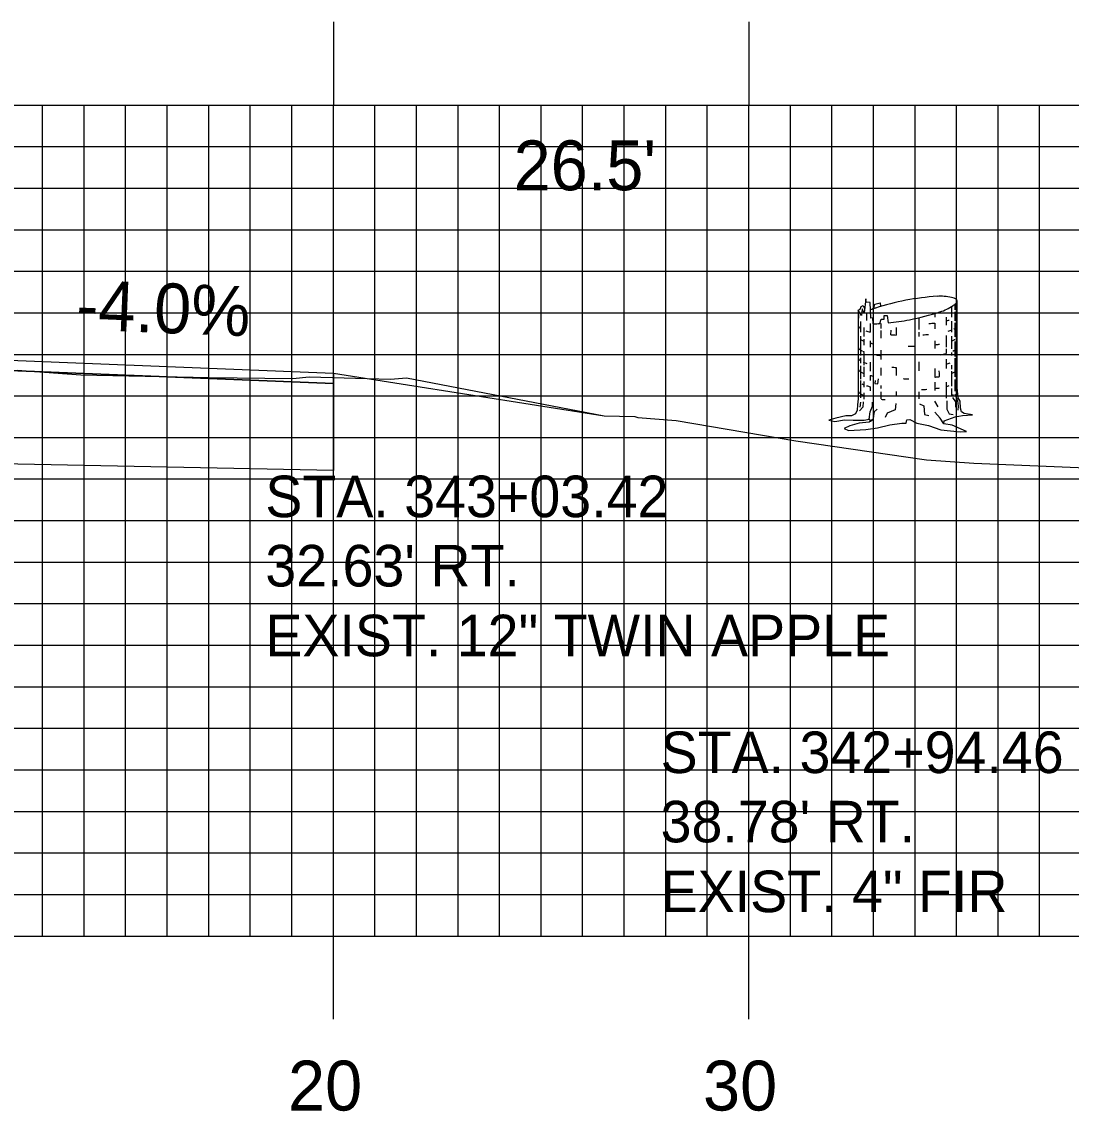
# Model space of a CAD drawing. Extents: x 1825147 to 1825490, y 442591 to 442811.
# Drawn here: x 1825324.86 to 1825350.12, y 442684.45 to 442710.67 of the extents above; entities that cross this region are included whole.
import ezdxf

# ---------------------------------------------------------------- set-up
doc = ezdxf.new("R2010")
doc.units = 0
for name, color, linetype in [('ANNOTATION', 7, 'Continuous'), ('D_Roadway_Edge_Shoulder', 7, 'Continuous'), ('D_Roadway_SubGrade', 7, 'Continuous'), ('D_Text_Monospaced', 7, 'Continuous'), ('D_Text_Standard', 7, 'Continuous'), ('H_V ANNOTATION', 7, 'Continuous'), ('MAJOR', 7, 'Continuous'), ('MINOR', 7, 'Continuous'), ('S_Roadway_Centerline', 7, 'Continuous'), ('S_Trees_Decid_Pay', 7, 'Continuous')]:
    doc.layers.add(name, color=color, linetype=linetype)

msp = doc.modelspace()

# ---------------------------------------------------------------- linework, layer by layer
at = {"layer": 'ANNOTATION'}
msp.add_line((1825332.361, 442702.213), (1825338.877, 442701.185), dxfattribs=at)
at = {"layer": 'D_Roadway_Edge_Shoulder'}
msp.add_lwpolyline([(1825324.361, 442702.533), (1825332.361, 442702.213), (1825332.361, 442701.963), (1825324.361, 442702.283)], close=True, dxfattribs=at)
at = {"layer": 'D_Roadway_SubGrade'}
msp.add_lwpolyline([(1825300.361, 442700.033), (1825292.361, 442699.873), (1825292.361, 442702.213), (1825292.361, 442701.963), (1825300.361, 442702.283), (1825312.361, 442702.523), (1825324.361, 442702.283), (1825332.361, 442701.963), (1825332.361, 442702.213), (1825332.361, 442699.873), (1825324.361, 442700.033), (1825312.361, 442700.273)], close=True, dxfattribs=at)
at = {"layer": 'MAJOR'}
for p, q in [((1825332.361, 442710.669), (1825332.361, 442708.665)), ((1825342.361, 442710.669), (1825342.361, 442708.665)), ((1825172.361, 442708.665), (1825452.361, 442708.665)), ((1825172.361, 442708.665), (1825452.361, 442708.665)), ((1825172.361, 442708.665), (1825452.361, 442708.665)), ((1825332.361, 442688.665), (1825332.361, 442708.665)), ((1825332.361, 442688.665), (1825332.361, 442708.665)), ((1825342.361, 442688.665), (1825342.361, 442708.665)), ((1825342.361, 442688.665), (1825342.361, 442708.665)), ((1825172.361, 442703.665), (1825452.361, 442703.665)), ((1825172.361, 442703.665), (1825452.361, 442703.665)), ((1825172.361, 442698.665), (1825452.361, 442698.665)), ((1825172.361, 442698.665), (1825452.361, 442698.665)), ((1825172.361, 442693.665), (1825452.361, 442693.665)), ((1825172.361, 442693.665), (1825452.361, 442693.665)), ((1825172.361, 442688.665), (1825452.361, 442688.665)), ((1825172.361, 442688.665), (1825452.361, 442688.665)), ((1825172.361, 442688.665), (1825452.361, 442688.665)), ((1825332.361, 442686.661), (1825332.361, 442688.665)), ((1825342.361, 442686.661), (1825342.361, 442688.665))]:
    msp.add_line(p, q, dxfattribs=at)
at = {"layer": 'MINOR'}
for p, q in [((1825325.361, 442688.665), (1825325.361, 442708.665)), ((1825325.361, 442688.665), (1825325.361, 442708.665)), ((1825326.361, 442688.665), (1825326.361, 442708.665)), ((1825326.361, 442688.665), (1825326.361, 442708.665)), ((1825327.361, 442688.665), (1825327.361, 442708.665)), ((1825327.361, 442688.665), (1825327.361, 442708.665)), ((1825328.361, 442688.665), (1825328.361, 442708.665)), ((1825328.361, 442688.665), (1825328.361, 442708.665)), ((1825329.361, 442688.665), (1825329.361, 442708.665)), ((1825329.361, 442688.665), (1825329.361, 442708.665)), ((1825330.361, 442688.665), (1825330.361, 442708.665)), ((1825330.361, 442688.665), (1825330.361, 442708.665)), ((1825331.361, 442688.665), (1825331.361, 442708.665)), ((1825331.361, 442688.665), (1825331.361, 442708.665)), ((1825333.361, 442688.665), (1825333.361, 442708.665)), ((1825333.361, 442688.665), (1825333.361, 442708.665)), ((1825334.361, 442688.665), (1825334.361, 442708.665)), ((1825334.361, 442688.665), (1825334.361, 442708.665)), ((1825335.361, 442688.665), (1825335.361, 442708.665)), ((1825335.361, 442688.665), (1825335.361, 442708.665)), ((1825336.361, 442688.665), (1825336.361, 442708.665)), ((1825336.361, 442688.665), (1825336.361, 442708.665)), ((1825337.361, 442688.665), (1825337.361, 442708.665)), ((1825337.361, 442688.665), (1825337.361, 442708.665)), ((1825338.361, 442688.665), (1825338.361, 442708.665)), ((1825338.361, 442688.665), (1825338.361, 442708.665)), ((1825339.361, 442688.665), (1825339.361, 442708.665)), ((1825339.361, 442688.665), (1825339.361, 442708.665)), ((1825340.361, 442688.665), (1825340.361, 442708.665)), ((1825340.361, 442688.665), (1825340.361, 442708.665)), ((1825341.361, 442688.665), (1825341.361, 442708.665)), ((1825341.361, 442688.665), (1825341.361, 442708.665)), ((1825343.361, 442688.665), (1825343.361, 442708.665)), ((1825343.361, 442688.665), (1825343.361, 442708.665)), ((1825344.361, 442688.665), (1825344.361, 442708.665)), ((1825344.361, 442688.665), (1825344.361, 442708.665)), ((1825345.361, 442688.665), (1825345.361, 442708.665)), ((1825345.361, 442688.665), (1825345.361, 442708.665)), ((1825346.361, 442688.665), (1825346.361, 442708.665)), ((1825346.361, 442688.665), (1825346.361, 442708.665)), ((1825347.361, 442688.665), (1825347.361, 442708.665)), ((1825347.361, 442688.665), (1825347.361, 442708.665)), ((1825348.361, 442688.665), (1825348.361, 442708.665)), ((1825348.361, 442688.665), (1825348.361, 442708.665)), ((1825349.361, 442688.665), (1825349.361, 442708.665)), ((1825349.361, 442688.665), (1825349.361, 442708.665)), ((1825172.361, 442707.665), (1825452.361, 442707.665)), ((1825172.361, 442707.665), (1825452.361, 442707.665)), ((1825172.361, 442706.665), (1825452.361, 442706.665)), ((1825172.361, 442706.665), (1825452.361, 442706.665)), ((1825172.361, 442705.665), (1825452.361, 442705.665)), ((1825172.361, 442705.665), (1825452.361, 442705.665)), ((1825172.361, 442704.665), (1825452.361, 442704.665)), ((1825172.361, 442704.665), (1825452.361, 442704.665)), ((1825172.361, 442702.665), (1825452.361, 442702.665)), ((1825172.361, 442702.665), (1825452.361, 442702.665)), ((1825172.361, 442701.665), (1825452.361, 442701.665)), ((1825172.361, 442701.665), (1825452.361, 442701.665)), ((1825172.361, 442700.665), (1825452.361, 442700.665)), ((1825172.361, 442700.665), (1825452.361, 442700.665)), ((1825172.361, 442699.665), (1825452.361, 442699.665)), ((1825172.361, 442699.665), (1825452.361, 442699.665)), ((1825172.361, 442697.665), (1825452.361, 442697.665)), ((1825172.361, 442697.665), (1825452.361, 442697.665)), ((1825172.361, 442696.665), (1825452.361, 442696.665)), ((1825172.361, 442696.665), (1825452.361, 442696.665)), ((1825172.361, 442695.665), (1825452.361, 442695.665)), ((1825172.361, 442695.665), (1825452.361, 442695.665)), ((1825172.361, 442694.665), (1825452.361, 442694.665)), ((1825172.361, 442694.665), (1825452.361, 442694.665)), ((1825172.361, 442692.665), (1825452.361, 442692.665)), ((1825172.361, 442692.665), (1825452.361, 442692.665)), ((1825172.361, 442691.665), (1825452.361, 442691.665)), ((1825172.361, 442691.665), (1825452.361, 442691.665)), ((1825172.361, 442690.665), (1825452.361, 442690.665)), ((1825172.361, 442690.665), (1825452.361, 442690.665)), ((1825172.361, 442689.665), (1825452.361, 442689.665)), ((1825172.361, 442689.665), (1825452.361, 442689.665))]:
    msp.add_line(p, q, dxfattribs=at)
at = {"layer": 'S_Roadway_Centerline'}
msp.add_lwpolyline([(1825324.751, 442702.284), (1825326.279, 442702.169), (1825329.368, 442702.108), (1825331.382, 442702.082), (1825331.777, 442702.121), (1825333.735, 442702.064), (1825334.12, 442702.1), (1825338.877, 442701.185), (1825339.617, 442701.17), (1825339.689, 442701.142), (1825340.614, 442701.071), (1825343.489, 442700.583), (1825346.64, 442700.125), (1825347.777, 442700.042), (1825350.864, 442699.915), (1825354.395, 442699.942), (1825358.764, 442699.53), (1825359.047, 442699.947), (1825360.34, 442700.695)], dxfattribs=at)
at = {"layer": 'S_Trees_Decid_Pay'}
for p, q in [((1825345.195, 442703.655), (1825345.195, 442703.48)), ((1825346.835, 442703.647), (1825346.835, 442703.56)), ((1825347.239, 442703.813), (1825347.239, 442703.56)), ((1825347.319, 442703.858), (1825347.319, 442703.737)), ((1825347.319, 442703.685), (1825347.319, 442703.472)), ((1825345.045, 442703.454), (1825345.045, 442703.2)), ((1825345.279, 442703.406), (1825345.279, 442703.201)), ((1825345.541, 442703.408), (1825345.541, 442703.288)), ((1825346.451, 442703.546), (1825346.451, 442703.265)), ((1825346.835, 442703.419), (1825346.835, 442703.28)), ((1825347.107, 442703.56), (1825347.107, 442703.368)), ((1825347.239, 442703.464), (1825347.239, 442703.2)), ((1825347.319, 442703.426), (1825347.319, 442703.088)), ((1825345.045, 442703.103), (1825345.045, 442702.634)), ((1825345.131, 442703.309), (1825345.131, 442703.097)), ((1825345.541, 442703.237), (1825345.541, 442703.052)), ((1825345.779, 442703.136), (1825345.784, 442703.243)), ((1825345.905, 442703.309), (1825345.905, 442703.129)), ((1825346.451, 442703.2), (1825346.451, 442703.097)), ((1825347.107, 442703.117), (1825347.107, 442702.84)), ((1825347.239, 442703.103), (1825347.239, 442702.794)), ((1825345.131, 442703.031), (1825345.131, 442702.883)), ((1825345.279, 442702.994), (1825345.279, 442702.84)), ((1825346.835, 442702.994), (1825346.835, 442702.802)), ((1825347.319, 442702.972), (1825347.319, 442702.611)), ((1825345.045, 442702.582), (1825345.045, 442702.449)), ((1825345.131, 442702.706), (1825345.131, 442702.405)), ((1825345.541, 442702.765), (1825345.541, 442702.537)), ((1825347.107, 442702.794), (1825347.107, 442702.685)), ((1825347.239, 442702.706), (1825347.239, 442702.639)), ((1825347.319, 442702.574), (1825347.319, 442702.125)), ((1825345.045, 442702.391), (1825345.045, 442702.065)), ((1825345.131, 442702.368), (1825345.131, 442702.125)), ((1825345.279, 442702.477), (1825345.279, 442702.257)), ((1825345.541, 442702.339), (1825345.541, 442702.154)), ((1825345.905, 442702.351), (1825345.905, 442702.154)), ((1825346.451, 442702.485), (1825346.451, 442702.265)), ((1825346.835, 442702.323), (1825346.835, 442702.115)), ((1825347.107, 442702.551), (1825347.107, 442702.323)), ((1825347.239, 442702.405), (1825347.239, 442702.308)), ((1825345.045, 442702.036), (1825345.045, 442701.617)), ((1825345.279, 442702.157), (1825345.279, 442702.036)), ((1825347.239, 442702.257), (1825347.239, 442701.897)), ((1825347.319, 442702.059), (1825347.319, 442701.777)), ((1825345.131, 442702.014), (1825345.131, 442701.874)), ((1825345.279, 442701.886), (1825345.279, 442701.787)), ((1825345.541, 442701.919), (1825345.541, 442701.842)), ((1825345.905, 442701.771), (1825345.905, 442701.668)), ((1825346.835, 442701.993), (1825346.835, 442701.794)), ((1825347.107, 442701.993), (1825347.107, 442701.61)), ((1825347.239, 442701.845), (1825347.239, 442701.678)), ((1825345.048, 442701.514), (1825345.034, 442701.396)), ((1825345.131, 442701.742), (1825345.131, 442701.586)), ((1825345.541, 442701.765), (1825345.541, 442701.592)), ((1825346.451, 442701.765), (1825346.451, 442701.592)), ((1825346.83, 442701.536), (1825346.91, 442701.405))]:
    msp.add_line(p, q, dxfattribs=at)
for points in [[(1825344.995, 442703.729), (1825344.995, 442701.592), (1825344.974, 442701.45), (1825344.968, 442701.324), (1825344.925, 442701.237), (1825344.833, 442701.188), (1825344.697, 442701.188), (1825344.453, 442701.132), (1825344.287, 442701.083), (1825344.429, 442701.052), (1825344.666, 442701.09), (1825344.876, 442701.077), (1825345.137, 442701.083), (1825345.261, 442701.101), (1825345.291, 442701.059), (1825345.354, 442701.101), (1825345.255, 442701.034), (1825345.02, 442701.009), (1825344.789, 442700.947), (1825344.659, 442700.877), (1825344.758, 442700.834), (1825345.18, 442700.853), (1825345.459, 442700.896), (1825345.757, 442700.972), (1825346.043, 442701.009), (1825346.148, 442701.009), (1825346.167, 442701.09), (1825346.235, 442701.096), (1825346.401, 442701.009), (1825346.688, 442700.953), (1825346.986, 442700.846), (1825347.445, 442700.797), (1825347.6, 442700.809), (1825347.258, 442700.96), (1825347.054, 442700.991), (1825347.066, 442701.065), (1825347.326, 442701.164), (1825347.501, 442701.195), (1825347.742, 442701.206), (1825347.544, 442701.244), (1825347.482, 442701.281), (1825347.458, 442701.367), (1825347.445, 442701.536), (1825347.4, 442701.622), (1825347.372, 442701.863), (1825347.372, 442703.949)], [(1825345.351, 442703.401), (1825345.343, 442703.546), (1825345.298, 442703.538), (1825345.283, 442703.912), (1825345.189, 442703.92), (1825345.174, 442704), (1825345.137, 442703.663), (1825345.092, 442703.758), (1825345.071, 442703.603), (1825344.995, 442703.729), (1825345.001, 442703.539)], [(1825345.373, 442703.767), (1825345.394, 442703.875), (1825345.526, 442703.906), (1825345.533, 442703.818)], [(1825344.995, 442703.729), (1825345.041, 442703.752), (1825345.063, 442703.817), (1825345.115, 442703.84), (1825345.148, 442703.765)], [(1825345.512, 442703.406), (1825345.549, 442703.509), (1825345.615, 442703.515), (1825345.615, 442703.597), (1825345.689, 442703.603), (1825345.714, 442703.423)], [(1825345.403, 442702.036), (1825345.394, 442701.962), (1825345.468, 442701.956), (1825345.483, 442702.073)], [(1825346.948, 442702.128), (1825346.947, 442702.205), (1825346.939, 442702.271)], [(1825345.115, 442701.521), (1825345.108, 442701.396), (1825345.026, 442701.302)], [(1825345.261, 442701.101), (1825345.279, 442701.281), (1825345.341, 442701.417), (1825345.335, 442701.517)], [(1825347.124, 442701.55), (1825347.124, 442701.345), (1825347.182, 442701.235), (1825347.279, 442701.219)], [(1825347.264, 442701.624), (1825347.336, 442701.521), (1825347.336, 442701.396)], [(1825347.321, 442701.705), (1825347.382, 442701.544), (1825347.396, 442701.419), (1825347.388, 442701.322)], [(1825345.452, 442701.349), (1825345.378, 442701.281), (1825345.359, 442701.182), (1825345.354, 442701.101)], [(1825345.903, 442701.485), (1825345.886, 442701.33), (1825345.689, 442701.25), (1825345.644, 442701.147)], [(1825346.469, 442701.476), (1825346.572, 442701.425), (1825346.587, 442701.219), (1825346.69, 442701.19)], [(1825347.054, 442700.991), (1825346.968, 442701.132), (1825346.836, 442701.275)]]:
    msp.add_lwpolyline(points, dxfattribs=at)
for centre, radius, start, end in [((1825347.285, 442697.948), 6.126, 100.7779, 107.8613), ((1825347.285, 442697.948), 6.126, 93.6944, 100.7779), ((1825346.974, 442702.764), 1.299, 78.2779, 93.6944), ((1825347.14, 442703.567), 0.48, 69.9843, 78.2779), ((1825347.013, 442704.237), 0.48, 303.2779, 311.5714), ((1825347.248, 442703.863), 0.164, 55.7779, 69.9843), ((1825347.222, 442704.001), 0.164, 311.5714, 325.7779), ((1825347.28, 442703.91), 0.107, 45.9547, 55.7779), ((1825347.31, 442703.941), 0.0645, 33.2779, 45.9547), ((1825347.269, 442703.969), 0.107, 325.7779, 335.6011), ((1825347.318, 442703.946), 0.0544, 22.46, 33.2779), ((1825347.308, 442703.952), 0.0645, 335.6011, 348.2779), ((1825347.325, 442703.949), 0.0467, 10.7779, 22.46), ((1825347.325, 442703.949), 0.0467, 359.0957, 10.7779), ((1825347.318, 442703.949), 0.0544, 348.2779, 359.0957), ((1825345.804, 442702.541), 1.299, 107.8613, 113.3069), ((1825345.082, 442709.516), 6.126, 280.7779, 287.8613), ((1825346.563, 442704.923), 1.299, 287.8613, 303.2779), ((1825347.318, 442703.623), 0.0554, 337.5, 348.3185), ((1825345.043, 442703.36), 0.0476, 180, 191.6815), ((1825345.05, 442703.362), 0.0554, 191.6815, 202.5), ((1825345.393, 442704.7), 1.299, 268.1289, 273.6944), ((1825345.082, 442709.516), 6.126, 273.6944, 274.0246), ((1825345.082, 442709.516), 6.126, 275.9147, 280.7779), ((1825346.185, 442709.299), 5.916, 274.9515, 276.3087), ((1825346.76, 442704.712), 1.292, 285.5651, 289.0916), ((1825347.232, 442703.692), 0.166, 301.67, 315), ((1825347.273, 442703.652), 0.109, 315, 324.8263), ((1825347.308, 442703.627), 0.0657, 324.8263, 337.5), ((1825347.317, 442703.362), 0.0554, 337.5, 348.3185), ((1825345.06, 442703.366), 0.0657, 202.5, 215.1737), ((1825345.095, 442703.391), 0.109, 215.1737, 225), ((1825345.136, 442703.431), 0.166, 225, 239.1924), ((1825345.608, 442704.451), 1.292, 250.6119, 255.2856), ((1825346.184, 442709.039), 5.916, 266.0776, 267.3043), ((1825346.184, 442709.039), 5.916, 273.5382, 274.8924), ((1825346.759, 442704.451), 1.292, 288.0829, 292.5), ((1825347.069, 442703.704), 0.484, 297.4162, 300.8076), ((1825347.231, 442703.431), 0.166, 300.8076, 315), ((1825347.272, 442703.391), 0.109, 315, 324.8263), ((1825347.307, 442703.366), 0.0657, 324.8263, 337.5), ((1825345.043, 442702.839), 0.0476, 180, 191.6815), ((1825345.05, 442702.841), 0.0554, 191.6815, 202.5), ((1825345.06, 442702.845), 0.0657, 202.5, 215.1737), ((1825345.136, 442703.168), 0.166, 237.0378, 239.1924), ((1825345.299, 442703.441), 0.484, 239.1924, 247.5), ((1825345.608, 442704.187), 1.292, 247.5, 248.3537), ((1825345.608, 442704.187), 1.292, 255.2856, 259.2632), ((1825346.184, 442708.775), 5.916, 270.1162, 271.7708), ((1825346.184, 442708.775), 5.916, 276.3184, 277.1546), ((1825346.759, 442704.187), 1.292, 277.1546, 278.3662), ((1825346.759, 442704.187), 1.292, 291.8071, 292.5), ((1825347.069, 442703.441), 0.484, 292.5, 300.8076), ((1825347.231, 442703.168), 0.166, 300.8076, 301.6001), ((1825347.307, 442702.845), 0.0657, 324.8263, 337.5), ((1825347.317, 442702.841), 0.0554, 337.5, 348.3185), ((1825345.043, 442702.582), 0.0476, 180, 191.6815), ((1825345.05, 442702.584), 0.0554, 191.6815, 202.5), ((1825345.06, 442702.588), 0.0657, 202.5, 215.1737), ((1825345.095, 442702.87), 0.109, 215.1737, 225), ((1825345.136, 442702.911), 0.166, 225, 239.1924), ((1825345.299, 442703.183), 0.484, 239.1924, 245.7725), ((1825345.608, 442703.93), 1.292, 247.5, 248.4842), ((1825345.608, 442703.93), 1.292, 261.8726, 262.8454), ((1825346.184, 442708.518), 5.916, 262.8454, 263.7595), ((1825346.759, 442703.93), 1.292, 279.2565, 285.6105), ((1825347.069, 442703.183), 0.484, 294.6372, 300.8076), ((1825347.231, 442702.911), 0.166, 300.8076, 315), ((1825347.272, 442702.87), 0.109, 315, 324.8263), ((1825347.307, 442702.588), 0.0657, 324.8263, 337.5), ((1825347.317, 442702.584), 0.0554, 337.5, 348.3185), ((1825345.043, 442702.316), 0.0476, 180, 191.6815), ((1825345.05, 442702.318), 0.0554, 191.6815, 202.5), ((1825345.06, 442702.322), 0.0657, 202.5, 215.1737), ((1825345.095, 442702.613), 0.109, 215.1737, 225), ((1825345.136, 442702.653), 0.166, 225, 239.1924), ((1825345.608, 442703.672), 1.292, 247.5, 251.799), ((1825346.184, 442708.26), 5.916, 266.2721, 267.3043), ((1825346.759, 442703.672), 1.292, 285.6105, 290.1001), ((1825347.231, 442702.653), 0.166, 302.0694, 315), ((1825347.272, 442702.613), 0.109, 315, 324.8263), ((1825347.317, 442702.318), 0.0554, 337.5, 348.3185), ((1825345.095, 442702.347), 0.109, 215.1737, 225), ((1825345.136, 442702.388), 0.166, 225, 239.1924), ((1825345.299, 442702.661), 0.484, 239.1924, 247.5), ((1825345.608, 442703.407), 1.292, 247.5, 248.3537), ((1825345.608, 442703.407), 1.292, 255.2856, 259.2463), ((1825346.184, 442707.995), 5.916, 268.9207, 270), ((1825346.184, 442707.995), 5.916, 270, 270.2757), ((1825346.184, 442707.995), 5.916, 276.3184, 277.1546), ((1825346.759, 442703.407), 1.292, 277.1546, 278.3795), ((1825347.069, 442702.661), 0.484, 292.5, 300.8076), ((1825347.231, 442702.388), 0.166, 300.8076, 302.0694), ((1825347.317, 442702.046), 0.0554, 337.5, 348.3185), ((1825345.043, 442701.787), 0.0476, 180, 191.6815), ((1825345.05, 442701.789), 0.0554, 191.6815, 202.5), ((1825345.299, 442702.389), 0.484, 242.734, 247.5), ((1825345.608, 442703.135), 1.292, 251.3664, 255.2856), ((1825346.184, 442707.723), 5.916, 273.2637, 274.461), ((1825346.184, 442707.723), 5.916, 276.3184, 277.1546), ((1825346.759, 442703.135), 1.292, 277.1546, 278.3662), ((1825346.759, 442703.135), 1.292, 285.6105, 289.1534), ((1825347.231, 442702.116), 0.166, 302.0694, 315), ((1825347.272, 442702.075), 0.109, 315, 324.8263), ((1825347.307, 442702.05), 0.0657, 324.8263, 337.5), ((1825345.06, 442701.793), 0.0657, 202.5, 215.1737), ((1825345.095, 442701.818), 0.109, 215.1737, 225), ((1825345.136, 442701.858), 0.166, 225, 239.1924), ((1825345.299, 442702.131), 0.484, 239.1924, 247.5), ((1825345.608, 442702.878), 1.292, 247.5, 248.3537), ((1825346.184, 442707.466), 5.916, 263.7831, 264.7656), ((1825346.769, 442702.881), 1.292, 291.3696, 292.0604), ((1825347.069, 442702.131), 0.484, 292.5, 296.5499)]:
    msp.add_arc(centre, radius, start, end, dxfattribs=at)

# ---------------------------------------------------------------- texts
at = {"layer": 'ANNOTATION'}
msp.add_text('-4.0%', height=1.2, rotation=357.7094, dxfattribs=at).set_placement((1825326.153, 442703.263))
at = {"layer": 'D_Text_Monospaced'}
for s, height, p in [('STA. 343+03.42', 0.99996, (1825330.723, 442698.746)), ("32.63' RT.", 1, (1825330.723, 442697.078)), ('EXIST. 12" TWIN APPLE', 0.99996, (1825330.723, 442695.398)), ('STA. 342+94.46', 0.99996, (1825340.237, 442692.587)), ("38.78' RT.", 1, (1825340.237, 442690.919)), ('EXIST. 4" FIR', 0.99996, (1825340.237, 442689.239))]:
    msp.add_text(s, height=height, dxfattribs=at).set_placement(p)
at = {"layer": 'D_Text_Standard'}
msp.add_text("26.5'", height=1.2, dxfattribs=at).set_placement((1825336.699, 442706.614))
at = {"layer": 'H_V ANNOTATION'}
for s, p in [('20', (1825331.269, 442684.465)), ('30', (1825341.258, 442684.465))]:
    msp.add_text(s, height=1.2, dxfattribs=at).set_placement(p)

doc.saveas('drawing.dxf')
